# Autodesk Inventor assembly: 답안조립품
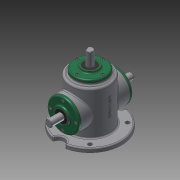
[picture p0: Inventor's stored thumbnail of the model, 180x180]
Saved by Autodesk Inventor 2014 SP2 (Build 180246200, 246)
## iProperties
Created: 2018-04
Part Number: 답안조립품
Document SubType Name: Assembly
Designer: 거성
Author: 거성
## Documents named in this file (16)
- C:\Users\거성\Desktop\480408V1005\답안조립품.iam
- C:\Users\거성\Desktop\480408V1005\본체.ipt
- C:\Users\거성\Desktop\480408V1005\커버.ipt
- C:\Users\거성\Desktop\480408V1005\베어링 6203.ipt
- C:\Users\거성\Desktop\480408V1005\오일 실.ipt
- 오일 실.ipt
- C:\Users\거성\Desktop\480408V1005\메인 축.ipt
- 메인 축.ipt
- C:\Users\거성\Desktop\480408V1005\키 5x5.ipt
- C:\Users\거성\Desktop\480408V1005\메인 베벨기어.ipt
- C:\Users\거성\Desktop\480408V1005\서브 축.ipt
- 서브 축.ipt
- C:\Users\거성\Desktop\480408V1005\키 4x4.ipt
- C:\Users\거성\Desktop\480408V1005\서브 베벨기어.ipt
- C:\Users\거성\Desktop\480408V1005\볼트 M4.ipt
- 볼트 M4.ipt
